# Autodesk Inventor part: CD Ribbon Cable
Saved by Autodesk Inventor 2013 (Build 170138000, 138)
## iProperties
Created: 2007-02
Part Number: CD Ribbon Cable
Document SubType Name: Modeling
Designer: floress
Density: 1 g/cm^3
Material: Allgemein
Author: floress
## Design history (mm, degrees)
workpoint "Work Point1"
workpoint "Work Point2"
sketch "RibbonCable1"
workpoint "Work Point3"
workpoint "Work Point4"
workpoint "Work Point5"
workpoint "Work Point6"
workpoint "Work Point7"
workpoint "Work Point8"
workpoint "Work Point9"
workpoint "Work Point10"
workpoint "Work Point11"
sketch "Sketch36"
  geometry: C1 r 0.445 at (0, -24.765)
  constraints: 1 centre point
sketch "Sketch37"
  geometry: C1 r 0.445 at (0, 24.765)
  constraints: 1 centre point
sketch "Sketch38"
  geometry: L1 (0, -25.4)-(0, 25.4)
  constraints: 2 end point
feature "SweepSrf32" dims "d31" = 0
feature "SweepSrf33" dims "d32" = 0
feature "SweepSrf34" dims "d33" = 0
sketch "Sketch39"
  geometry: C1 r 0.444 at (-24.765, 0)
  constraints: 1 centre point
sketch "Sketch40"
  geometry: C1 r 0.444 at (24.765, 0)
  constraints: 1 centre point
sketch "Sketch41"
  geometry: L1 (-25.4, 0)-(25.4, 0)
  constraints: 2 end point
feature "SweepSrf35" dims "d34" = 0
feature "SweepSrf36" dims "d35" = 0
feature "SweepSrf37" dims "d36" = 0
sketch "Sketch42"
  geometry: C1 r 0.444 at (24.765, 0)
  constraints: 1 centre point
sketch "Sketch43"
  geometry: C1 r 0.444 at (-24.765, 0)
  constraints: 1 centre point
sketch "Sketch44"
  geometry: L1 (25.4, 0)-(-25.4, 0)
  constraints: 2 end point
feature "SweepSrf38" dims "d37" = 0
feature "SweepSrf39" dims "d38" = 0
feature "SweepSrf40" dims "d39" = 0
sketch "Sketch48"
  geometry: L1 (25.4, 25.4)-(25.4, -25.4); L2 (25.4, -25.4)-(-25.4, 25.4); L3 (-25.4, 25.4)-(25.4, 25.4)
  constraints: 6 end point
patch "Boundary Patch2" sketch "Sketch48"
sketch "3D Sketch22"
sketch "Sketch49"
  geometry: C1 r 0.445 at (0, 0)
  constraints: 1 centre point
feature "SweepSrf43" sketch "3D Sketch22", "Sketch49" dims "d42" = 0
sketch "3D Sketch23"
sketch "Sketch50"
  geometry: C1 r 0.445 at (0, 0)
  constraints: 1 centre point
feature "SweepSrf44" sketch "3D Sketch23", "Sketch50" dims "d43" = 0
workpoint "Work Point12"
workpoint "Work Point13"
workpoint "Work Point14"
workpoint "Work Point15"
sketch "Sketch57"
  geometry: L1 (25.4, 25.4)-(25.4, -25.4); L2 (25.4, -25.4)-(-25.4, 25.4); L3 (-25.4, 25.4)-(25.4, 25.4)
  constraints: 6 end point
patch "Boundary Patch5" sketch "Sketch57"
sketch "3D Sketch28"
sketch "Sketch58"
  geometry: C1 r 0.445 at (0, 0)
  constraints: 1 centre point
feature "SweepSrf49" sketch "3D Sketch28", "Sketch58" dims "d48" = 0
sketch "3D Sketch29"
sketch "Sketch59"
  geometry: C1 r 0.445 at (0, 0)
  constraints: 1 centre point
feature "SweepSrf50" sketch "3D Sketch29", "Sketch59" dims "d49" = 0
body "Srf1"
body "Srf2"
body "Srf3"
body "Srf4"
body "Srf5"
body "Srf6"
body "Srf7"
body "Srf8"
body "Srf9"
body "Srf10"
body "Srf11"
body "Srf12"
body "Srf13"
body "Srf14"
body "Srf15"
